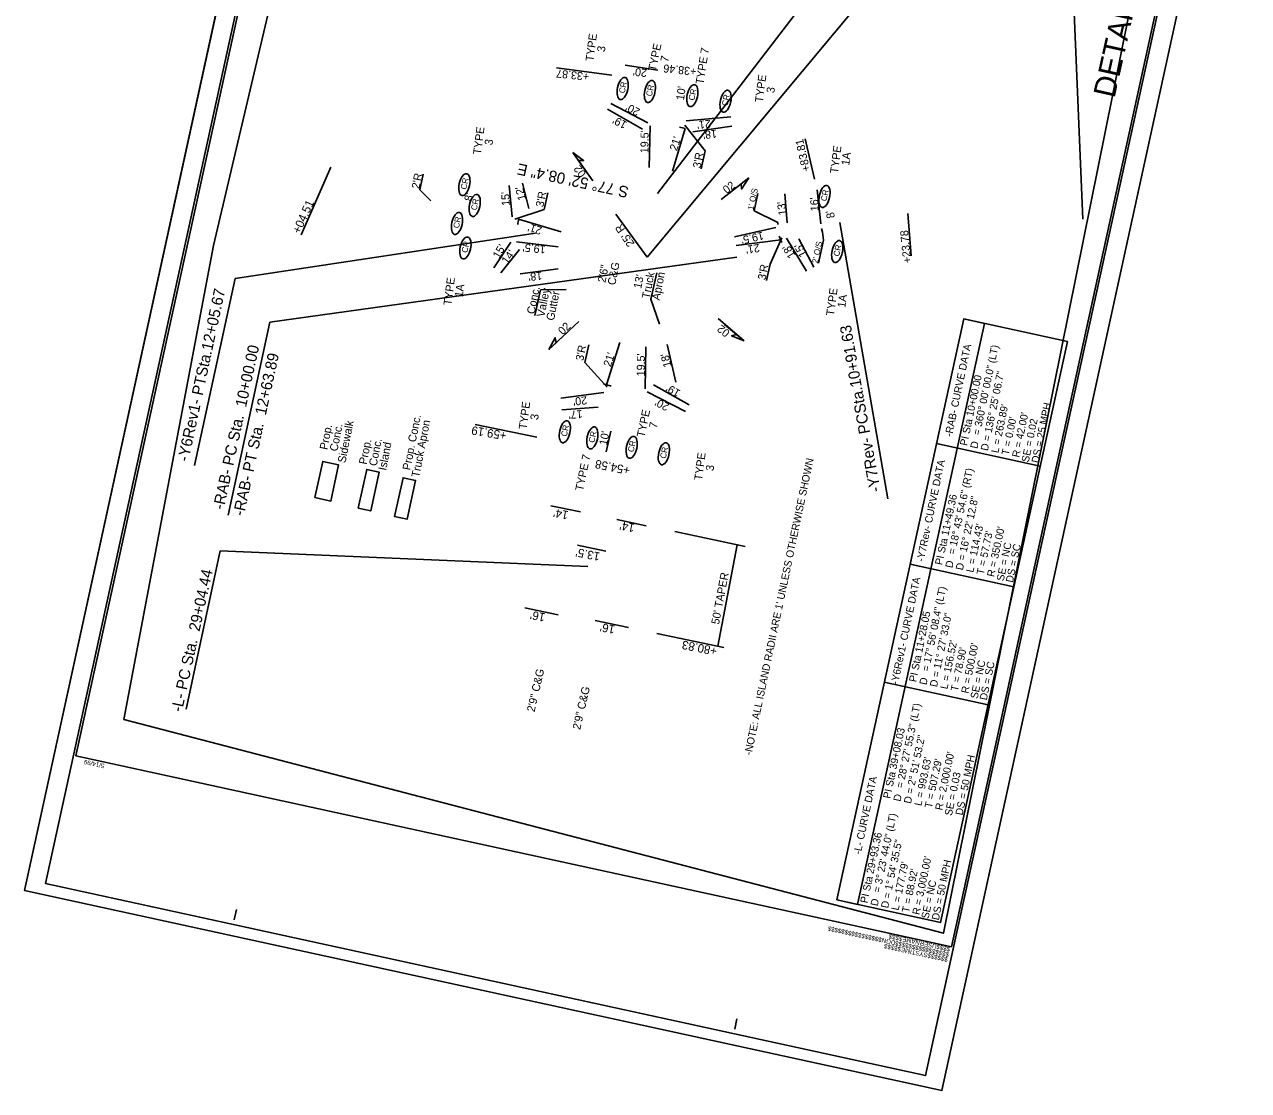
# Model space of a CAD drawing. Extents: x 1616330 to 1616903, y 901240 to 902105.
# Drawn here: x 1616330 to 1616903, y 901240 to 901740 of the extents above; entities that cross this region are included whole.
import ezdxf

# ---------------------------------------------------------------- set-up
doc = ezdxf.new("R2010")
doc.units = 0
for name, color, linetype in [('Prop Conc 4in Sidewalk', 7, 'Continuous'), ('Prop Conc 5in Monolithic Keyed In Island', 7, 'Continuous'), ('Prop Dimension', 7, 'Continuous'), ('Prop Dimension Text', 7, 'Continuous'), ('Prop Horizontal Alignment Curve and Spiral Data', 7, 'Continuous'), ('Prop Horizontal Alignment Direction Label', 7, 'Continuous'), ('Prop Horizontal Alignment Station Label', 7, 'Continuous'), ('Prop Lane Lines', 7, 'Continuous'), ('Prop Superelevation  Arrow CELL', 7, 'Continuous'), ('Prop WCC CELL', 7, 'Continuous'), ('Sheet Border Standard 30in CELL', 7, 'Continuous'), ('Sheet Clip Boundary CELL', 7, 'Continuous'), ('Sheet Cutting Line CELL', 7, 'Continuous'), ('Sheet Plot Border Inside CELL', 7, 'Continuous'), ('Sheet Plot Border Outside CELL', 7, 'Continuous')]:
    doc.layers.add(name, color=color, linetype=linetype)

msp = doc.modelspace()

# ---------------------------------------------------------------- linework, layer by layer
at = {"layer": 'Prop Conc 4in Sidewalk'}
msp.add_lwpolyline([(1616465.8, 901518.29), (1616469.5, 901535.23), (1616476.92, 901533.61), (1616473.23, 901516.67)], close=True, dxfattribs=at)
at = {"layer": 'Prop Conc 5in Monolithic Keyed In Island'}
for points in [[(1616486.1, 901513.37), (1616490.06, 901531.5), (1616495.95, 901530.22), (1616491.99, 901512.09)], [(1616503.17, 901509.5), (1616507.13, 901527.63), (1616513.01, 901526.35), (1616509.05, 901508.21)]]:
    msp.add_lwpolyline(points, close=True, dxfattribs=at)
at = {"layer": 'Prop Dimension'}
for p, q in [((1616473.27, 901673.25), (1616459.3, 901641.44)), ((1616516.55, 901669.91), (1616514.95, 901662.58)), ((1616556.89, 901664.63), (1616558.31, 901649.92)), ((1616514.95, 901662.58), (1616520.06, 901657.36)), ((1616573.29, 901653.35), (1616574.93, 901661.25)), ((1616573.29, 901653.35), (1616559.56, 901648.89)), ((1616581.23, 901642.9), (1616561.22, 901648.81)), ((1616552.93, 901623.65), (1616561.61, 901634.56)), ((1616663.62, 901496.22), (1616654.53, 901448.62))]:
    msp.add_line(p, q, dxfattribs=at)
at = {"layer": 'Prop Dimension Text'}
for p, q in [((1616626.52, 901718.67), (1616611.11, 901721.08)), ((1616579, 901719.79), (1616604.86, 901716.41)), ((1616604.39, 901703), (1616621.82, 901693.99)), ((1616602.94, 901700.34), (1616619.33, 901691.07)), ((1616622.4, 901672.99), (1616622.82, 901692.63)), ((1616648.62, 901680.82), (1616639.1, 901692.96)), ((1616660.67, 901696.76), (1616639.76, 901694.86)), ((1616661.18, 901692.47), (1616642.89, 901689.74)), ((1616633.4, 901671.28), (1616639.32, 901691.35)), ((1616699.83, 901667.62), (1616695.57, 901686.54)), ((1616646.78, 901672.4), (1616648.62, 901680.82)), ((1616563.09, 901665.7), (1616566.06, 901653.9)), ((1616671.63, 901652.74), (1616673.39, 901660.82)), ((1616685.97, 901660.7), (1616687.14, 901647.1)), ((1616701.15, 901662.58), (1616702.87, 901646.7)), ((1616682.7, 901647.24), (1616671.63, 901652.74)), ((1616743.55, 901651.46), (1616745.26, 901631.59)), ((1616621.5, 901631), (1616606.8, 901651.21)), ((1616682.7, 901647.24), (1616682.65, 901646.33)), ((1616662.42, 901640.47), (1616681.7, 901644.93)), ((1616679.12, 901627.79), (1616684.53, 901640.11)), ((1616696.22, 901624.47), (1616686.77, 901639.99)), ((1616703.57, 901642.74), (1616703.21, 901644.43)), ((1616704.06, 901639.06), (1616703.57, 901642.74)), ((1616549.62, 901626.07), (1616557.6, 901638)), ((1616579.79, 901635.92), (1616560.28, 901638.22)), ((1616663.15, 901636.43), (1616684.18, 901639.17)), ((1616699.59, 901626.39), (1616692.62, 901639.54)), ((1616701.71, 901628.27), (1616704.06, 901639.06)), ((1616579.85, 901625.6), (1616562, 901623.28)), ((1616625.95, 901623.71), (1616623.24, 901611.28)), ((1616677.45, 901620.1), (1616679.12, 901627.79)), ((1616568.88, 901603.66), (1616571.5, 901615.66)), ((1616571.5, 901615.66), (1616583.51, 901615.93)), ((1616623.24, 901611.28), (1616627.34, 901599.61)), ((1616592.31, 901581.69), (1616594.11, 901589.92)), ((1616608.75, 901590.98), (1616602.45, 901571.19)), ((1616620.82, 901589), (1616620.5, 901569.35)), ((1616630.87, 901590.06), (1616634.9, 901572.45)), ((1616592.31, 901581.69), (1616602.81, 901570.06)), ((1616641.17, 901561.75), (1616624.5, 901571.17)), ((1616581.01, 901564.97), (1616601.22, 901567.57)), ((1616639.47, 901558.6), (1616621.44, 901567.87)), ((1616581.56, 901559.48), (1616598.54, 901560.76)), ((1616569.85, 901546.67), (1616540.95, 901552.57)), ((1616602.27, 901539.72), (1616604.41, 901549.44)), ((1616576.41, 901514.48), (1616590.18, 901511.59)), ((1616607.28, 901508.02), (1616621.06, 901505.13)), ((1616634.4, 901502.34), (1616667.41, 901495.43)), ((1616588.91, 901496.01), (1616602.1, 901493.14)), ((1616564.1, 901466.7), (1616579.76, 901463.42)), ((1616597.07, 901460.65), (1616612.73, 901457.37)), ((1616626.02, 901454.59), (1616657.48, 901448))]:
    msp.add_line(p, q, dxfattribs=at)
at = {"layer": 'Prop Horizontal Alignment Curve and Spiral Data'}
for p, q in [((1616621.5, 901631), (1616764.08, 901801.92)), ((1616825.59, 901648.89), (1616819.68, 901790.61)), ((1616626.32, 901660.79), (1616713.55, 901774.6)), ((1616711.69, 901647.23), (1616734.25, 901517.75)), ((1616569.17, 901642.25), (1616428.51, 901621.07)), ((1616663.5, 901631), (1616444.66, 901600.49)), ((1616428.51, 901621.07), (1616409.37, 901533.39)), ((1616444.66, 901600.49), (1616425.21, 901510.13)), ((1616757.04, 901543.67), (1616805.65, 901533.06)), ((1616421.47, 901493.4), (1616405.52, 901419.06)), ((1616593.64, 901486.05), (1616421.47, 901493.4)), ((1616744.69, 901487.06), (1616793.3, 901476.45)), ((1616732.61, 901431.74), (1616781.22, 901421.13))]:
    msp.add_line(p, q, dxfattribs=at)
for points in [[(1616710.35, 901329.75), (1616769.79, 901602.05), (1616779.53, 901599.92), (1616720.09, 901327.63)], [(1616710.35, 901329.75), (1616769.79, 901602.05), (1616818.4, 901591.44), (1616758.96, 901319.14)]]:
    msp.add_lwpolyline(points, close=True, dxfattribs=at)
at = {"layer": 'Prop Lane Lines'}
msp.add_line((1616683.37, 901640.88), (1616684.59, 901637.91), dxfattribs=at)
for centre, radius, start, end in [((1616627.06, 901640.49), 52.32, 76.44378, 79.43225), ((1616626.69, 901637.63), 66.41, 170.24203, 172.45336), ((1616616.3, 901617.46), 48.29, 251.62516, 256.04922)]:
    msp.add_arc(centre, radius, start, end, dxfattribs=at)
at = {"layer": 'Prop Superelevation  Arrow CELL'}
for p, q in [((1616596.05, 901666.78), (1616586.6, 901680.06)), ((1616586.6, 901680.06), (1616593.54, 901670.27)), ((1616656.11, 901658.03), (1616669.18, 901668.24)), ((1616669.18, 901668.24), (1616659.76, 901660.82)), ((1616589.53, 901600.91), (1616575.47, 901587.68)), ((1616654.73, 901602.29), (1616666.9, 901591.76)), ((1616575.47, 901587.68), (1616584.18, 901595.93)), ((1616666.9, 901591.76), (1616657.73, 901599.51))]:
    msp.add_line(p, q, dxfattribs=at)
for points in [[(1616586.6, 901680.06), (1616591.7, 901676.32), (1616589.28, 901676.29)], [(1616669.18, 901668.24), (1616665.71, 901662.96), (1616665.55, 901665.38)], [(1616666.9, 901591.76), (1616661.02, 901594.11), (1616663.36, 901594.75)], [(1616575.47, 901587.68), (1616578.45, 901593.26), (1616578.83, 901590.86)]]:
    msp.add_lwpolyline(points, close=True, dxfattribs=at)
at = {"layer": 'Prop WCC CELL'}
for centre in [(1616610.01, 901710.09), (1616622.76, 901708.67), (1616642.65, 901706.74), (1616658.22, 901704.11), (1616535.85, 901665), (1616704.58, 901659.49), (1616540.69, 901655.25), (1616532.37, 901646.82), (1616536.32, 901635.31), (1616710.54, 901633.64), (1616582.91, 901549.19), (1616595.82, 901546.27), (1616614.2, 901541.87), (1616629.31, 901538.86)]:
    msp.add_ellipse(centre, major_axis=(1.12, 5.14), ratio=0.462467, dxfattribs=at)
at = {"layer": 'Sheet Border Standard 30in CELL'}
for p, q in [((1616353.82, 901397.71), (1616353.82, 901397.71)), ((1616428.02, 901320.3), (1616429.09, 901325.19)), ((1616662.5, 901269.12), (1616663.57, 901274))]:
    msp.add_line(p, q, dxfattribs=at)
msp.add_lwpolyline([(1616481.7, 901983.51), (1616353.74, 901397.31), (1616764.08, 901307.74), (1616892.04, 901893.94)], close=True, dxfattribs=at)
at = {"layer": 'Sheet Clip Boundary CELL'}
msp.add_lwpolyline([(1616418.32, 901636.55), (1616453.3, 901785.32), (1616537.99, 901872.41), (1616557.7, 901949.17), (1616874.13, 901878.62), (1616760.29, 901314.11), (1616376.33, 901414.34)], close=True, dxfattribs=at)
at = {"layer": 'Sheet Cutting Line CELL'}
for p, q in [((1616473.38, 901992.29), (1616329.72, 901334.18)), ((1616759.6, 901240.35), (1616903.26, 901898.45)), ((1616329.72, 901334.18), (1616759.6, 901240.35))]:
    msp.add_line(p, q, dxfattribs=at)
at = {"layer": 'Sheet Plot Border Inside CELL'}
msp.add_lwpolyline([(1616481.77, 901988.61), (1616339.61, 901337.35), (1616751.94, 901247.34), (1616894.1, 901898.61)], close=True, dxfattribs=at)
at = {"layer": 'Sheet Plot Border Outside CELL'}
msp.add_lwpolyline([(1616473.38, 901992.29), (1616329.72, 901334.18), (1616759.6, 901240.35), (1616903.26, 901898.45)], close=True, dxfattribs=at)

# ---------------------------------------------------------------- texts
at = {"layer": 'Prop Dimension'}
for s, rotation, p in [('+38.46', 173.86253, (1616644.68, 901719.78)), ('+33.87', 173.86253, (1616594.46, 901717.36)), ("2'R", 78.8222, (1616514.72, 901662.84)), ("8'", 78.8222, (1616539.37, 901657)), ("21'", 163.20688, (1616572.53, 901644.97)), ("19.5'", 173.86253, (1616574.07, 901636.32)), ("18'", 185.93949, (1616572.1, 901624.2)), ("20'", 185.93949, (1616593.14, 901565.81)), ('Sidewalk', 78.8222, (1616480.1, 901534.33)), ('Prop. Conc.', 78.8222, (1616510.43, 901530.91)), ('Truck Apron', 78.8222, (1616514.61, 901527.54)), ("17'", 183.97181, (1616591.07, 901559.37)), ('Prop.', 78.8222, (1616471.62, 901540.51)), ('Conc.', 78.8222, (1616476.32, 901539.76)), ("10'", 78.8222, (1616602.59, 901542.59)), ('Prop.', 78.8222, (1616490.01, 901533.61)), ('Conc.', 78.8222, (1616494.71, 901532.87)), ('Island', 78.8222, (1616499.14, 901530.8)), ("50' TAPER", 79.27292, (1616655.14, 901458.64)), ('2\'9" C&G', 76.97013, (1616568.69, 901417.58)), ('2\'9" C&G', 76.97013, (1616590.08, 901409.27))]:
    msp.add_text(s, height=3.75, rotation=rotation, dxfattribs=at).set_placement(p)
at = {"layer": 'Prop Dimension Text'}
for s, height, rotation, p in [('TYPE', 3.75, 82.48343, (1616596.28, 901722.61)), ('3', 3.75, 82.48343, (1616601.65, 901727.01)), ('TYPE ', 3.75, 78.11478, (1616625.52, 901717.99)), ('TYPE 7', 3.75, 81.05395, (1616647.82, 901711.81)), ('7', 3.75, 78.11478, (1616631.27, 901722.24)), ("20'", 3.75, 173.16709, (1616621.6, 901719.1)), ('TYPE', 3.75, 82.48343, (1616675.65, 901703.37)), ("10'", 3.75, 82.48343, (1616638.73, 901704.37)), ('3', 3.75, 82.48343, (1616681.03, 901707.77)), ("20'", 3.75, 151.96111, (1616618.49, 901700.24)), ('TYPE', 3.75, 82.48343, (1616543.58, 901678.93)), ("19'", 3.75, 151.96111, (1616612.41, 901694.19)), ("21'", 3.75, 186.13724, (1616651.12, 901695.45)), ('3', 3.75, 82.48343, (1616548.95, 901683.33)), ("19.5'", 3.75, 89.25323, (1616622.05, 901679.73)), ("21'", 3.75, 71.81665, (1616635.4, 901680.59)), ("18'", 3.75, 186.13724, (1616653.95, 901690.77)), ('+83.81', 3.75, 102.59072, (1616697.88, 901671.63)), ("3'R", 3.75, 78.8222, (1616646.48, 901672.49)), ('TYPE', 3.75, 82.48343, (1616710.84, 901670.08)), ('1A', 3.75, 82.48343, (1616716.14, 901673.87)), ("12'", 3.75, 104.73887, (1616564.76, 901658.17)), ("1' O/S", 2.812, 77.92825, (1616671.25, 901652.88)), ('+04.51', 4, 65.61117, (1616458.71, 901641.65)), ("15'", 3.75, 92.26611, (1616557.11, 901655.15)), ("3'R", 3.75, 78.8222, (1616572.87, 901654.25)), ("16'", 3.75, 92.57432, (1616701.85, 901652.62)), ("13'", 3.75, 97.26663, (1616686.85, 901650.81)), ("8'", 3.75, 103.26568, (1616709.51, 901649.67)), ("25' R", 3.75, 124.39262, (1616615.75, 901637.41)), ("19.5'", 3.75, 192.69385, (1616675.64, 901643.02)), ('+23.78', 3.75, 95.6725, (1616745.22, 901628.39)), ("15'", 3.75, 59.69947, (1616552.1, 901630)), ("14'", 3.75, 53.78477, (1616555.94, 901627.45)), ("21'", 3.75, 188.66453, (1616673.88, 901637.24)), ("18'", 3.75, 121.77974, (1616691.19, 901631.87)), ("15'", 3.75, 116.7086, (1616696.46, 901632.11)), ("2' O/S", 2.812, 78.17648, (1616701.41, 901627.96)), ('C&G', 3.75, 78.8222, (1616606.52, 901617.65)), ('2\'6"', 3.75, 78.8222, (1616601.9, 901618.84)), ("13'", 3.75, 78.8222, (1616618.69, 901616.05)), ('Truck', 3.75, 78.8222, (1616622.6, 901611.32)), ('Apron', 3.75, 78.8222, (1616627.3, 901610.6)), ("3'R", 3.75, 78.8222, (1616676.91, 901620.05)), ('TYPE', 3.75, 82.48343, (1616529.72, 901608.25)), ('1A', 3.75, 82.48343, (1616535.02, 901612.05)), ('Conc.', 3.75, 78.8222, (1616568.71, 901604.12)), ('Valley', 3.75, 78.8222, (1616573.29, 901602.75)), ('Gutter', 3.75, 78.8222, (1616577.8, 901601.04)), ('TYPE', 3.75, 82.48343, (1616709.02, 901603.37)), ('1A', 3.75, 82.48343, (1616714.31, 901607.17)), ("3'R", 3.75, 78.8222, (1616591.55, 901582.2)), ("21'", 3.75, 71.81665, (1616604.4, 901579.33)), ("19.5'", 3.75, 89.25323, (1616620.33, 901575.13)), ("18'", 3.75, 105.04812, (1616632.92, 901579.95)), ("19'", 3.75, 149.35687, (1616637.41, 901568.33)), ('TYPE', 3.75, 82.48343, (1616564.99, 901550.11)), ('TYPE ', 3.75, 78.11478, (1616620.22, 901546.33)), ("20'", 3.75, 153.12968, (1616632.2, 901562.04)), ('3', 3.75, 82.48343, (1616570.37, 901554.51)), ('7', 3.75, 78.11478, (1616625.97, 901550.58)), ('+59.19', 4, 170.49871, (1616555.82, 901549.14)), ('TYPE 7', 3.75, 78.11478, (1616591.39, 901521.19)), ('TYPE', 3.75, 82.48343, (1616647.2, 901526.19)), ("-NOTE: ALL ISLAND RADII ARE 1' UNLESS OTHERWISE SHOWN", 3.5, 78.15785, (1616670.36, 901397.31)), ('+54.58', 4, 168.64248, (1616613.73, 901532.84)), ('3', 3.75, 82.48343, (1616652.57, 901530.59)), ("14'", 4, 168.64248, (1616584.85, 901511.88)), ("14'", 4, 168.64248, (1616615.93, 901505.88)), ("13.5'", 4, 168.64248, (1616599.67, 901492.45)), ("16'", 4, 168.64248, (1616573.99, 901463.96)), ("16'", 4, 168.64248, (1616606.7, 901458.23)), ('+80.83', 4, 168.64248, (1616654.48, 901448.08))]:
    msp.add_text(s, height=height, rotation=rotation, dxfattribs=at).set_placement(p)
at = {"layer": 'Prop Horizontal Alignment Curve and Spiral Data'}
for s, rotation, p in [('-RAB- CURVE DATA', 78.15785, (1616764.3, 901546.61)), ('= 360%%d 00\' 00.0" (LT)', 78.18721, (1616777.39, 901547.35)), ('D = 136%%d 25\' 06.7"', 78.18721, (1616781.11, 901540.01)), ('PI Sta 10+00.00', 78.18721, (1616771.39, 901542.39)), ("L = 263.89'", 78.18721, (1616786.01, 901538.98)), ('DS = 25 MPH', 78.15785, (1616804.91, 901534.31)), ("T = 0.00'", 78.18721, (1616790.9, 901537.96)), ("R = 42.00'", 78.18721, (1616795.8, 901536.94)), ('SE = 0.02', 78.15785, (1616800.25, 901534.64)), ('D', 78.18721, (1616776.22, 901541.03)), ('-Y7Rev- CURVE DATA', 78.15785, (1616751.08, 901488.02)), ('= 18%%d 43\' 54.6" (RT)', 77.92762, (1616765.7, 901491.39)), ('PI Sta 11+49.36', 77.92762, (1616759.69, 901486.46)), ('D = 16%%d 22\' 12.8"', 77.92762, (1616769.39, 901484.03)), ("L = 114.43'", 77.92762, (1616774.28, 901482.99)), ("T = 57.73'", 77.92762, (1616779.17, 901481.94)), ("R = 350.00'", 77.92762, (1616784.06, 901480.9)), ('SE = NC', 78.15785, (1616788.53, 901478.97)), ('DS = SC', 78.15785, (1616792.86, 901478.26)), ('D', 77.92762, (1616764.5, 901485.08)), ('-Y6Rev1- CURVE DATA', 78.15785, (1616739.01, 901430.46)), ('= 17%%d 56\' 08.4" (LT)', 78.487, (1616753.51, 901436.61)), ('PI Sta 11+28.05', 78.487, (1616747.54, 901431.61)), ('D = 11%%d 27\' 33.0"', 78.487, (1616757.28, 901429.29)), ("L = 156.52'", 78.487, (1616762.17, 901428.29)), ("T = 78.90'", 78.487, (1616767.07, 901427.29)), ("R = 500.00'", 78.487, (1616771.97, 901426.29)), ('SE = NC', 78.15785, (1616776.29, 901423.75)), ('DS = SC', 78.15785, (1616780.61, 901423.11)), ('D', 78.487, (1616752.38, 901430.29)), ('= 28%%d 27\' 55.3" (LT)', 78.10542, (1616741.36, 901381.95)), ('PI Sta 39+08.03', 78.10542, (1616735.36, 901376.99)), ('D = 2%%d 51\' 53.2"', 78.10542, (1616745.07, 901374.6)), ("R = 2,000.00'", 78.10542, (1616759.75, 901371.51)), ("L = 993.63'", 78.10542, (1616749.96, 901373.57)), ("T = 507.29'", 78.10542, (1616754.86, 901372.54)), ('DS = 50 MPH', 78.15785, (1616769.25, 901369.16)), ('SE = 0.03', 78.15785, (1616764.22, 901368.94)), ('-L- CURVE DATA', 78.15785, (1616721.57, 901350.83)), ('D', 78.10542, (1616740.18, 901375.63)), ('= 3%%d 23\' 44.0" (LT)', 78.15785, (1616730.65, 901332.93)), ('PI Sta 29+93.36', 78.15785, (1616724.65, 901327.96)), ('D = 1%%d 54\' 35.5"', 78.15785, (1616734.37, 901325.58)), ("L = 177.79'", 78.15785, (1616739.27, 901324.56)), ("R = 3,000.00'", 78.15785, (1616749.05, 901322.5)), ('DS = 50 MPH', 78.15785, (1616758.14, 901319.97)), ("T = 88.92'", 78.15785, (1616744.16, 901323.53)), ('SE = NC', 78.15785, (1616753.31, 901320.61)), ('D', 78.15785, (1616729.48, 901326.61))]:
    msp.add_text(s, height=3.5, rotation=rotation, dxfattribs=at).set_placement(p)
at = {"layer": 'Prop Horizontal Alignment Direction Label'}
msp.add_text('S 77%%d 52\' 08.4" E', height=5.25, rotation=167.86901, dxfattribs=at).set_placement((1616613.17, 901663.87))
at = {"layer": 'Prop Horizontal Alignment Station Label'}
for s, height, rotation, p in [('DETAIL OF ROUNDABOUT', 10.2539, 77.41846, (1616840.46, 901705.26)), ('-Y6Rev1- PTSta.12+05.67', 5.25, 77.86901, (1616406.5, 901534.95)), ('-Y7Rev- PCSta.10+91.63', 5.25, 100.20085, (1616730.92, 901521.37)), ('-RAB- PC Sta.  10+00.00', 5.25, 77.71405, (1616423.05, 901512.36)), ('-RAB- PT Sta.  12+63.89', 5.25, 77.71405, (1616432.48, 901509.38)), ('-L- PC Sta.  29+04.44', 5.25, 77.71031, (1616403.49, 901417.54))]:
    msp.add_text(s, height=height, rotation=rotation, dxfattribs=at).set_placement(p)
at = {"layer": 'Prop Superelevation  Arrow CELL'}
for rotation, p in [(127.66121, (1616593.12, 901670.22)), (37.86031, (1616658.74, 901660.55)), (44.35814, (1616581.94, 901594.33)), (141.25427, (1616660.54, 901596.1))]:
    msp.add_text('02', height=3.75, rotation=rotation, dxfattribs=at).set_placement(p)
at = {"layer": 'Prop WCC CELL'}
for p in [(1616610.89, 901707.64), (1616623.64, 901706.21), (1616643.53, 901704.29), (1616659.11, 901701.66), (1616536.74, 901662.55), (1616541.57, 901652.8), (1616705.46, 901657.04), (1616533.25, 901644.37), (1616537.2, 901632.86), (1616711.42, 901631.18), (1616583.8, 901546.73), (1616596.7, 901543.82), (1616615.08, 901539.42), (1616630.19, 901536.41)]:
    msp.add_text('CR', height=2.812, rotation=77.68623, dxfattribs=at).set_placement(p)
at = {"layer": 'Sheet Border Standard 30in CELL'}
for s, p in [('5/14/99', (1616367.3, 901393.43)), ('$$$$$$$$$$$$$$$$DGN$$$$$$$$$$$$$$$$', (1616763.14, 901305.02)), ('$$$$USERNAME$$$$', (1616763.63, 901307.49)), ('$$$$$$SYSTIME$$$$$', (1616762.54, 901302.67))]:
    msp.add_text(s, height=2.1, rotation=167.68623, dxfattribs=at).set_placement(p)

doc.saveas('drawing.dxf')
